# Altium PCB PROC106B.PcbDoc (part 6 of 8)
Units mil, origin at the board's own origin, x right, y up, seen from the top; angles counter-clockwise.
Board outline 4498.18 x 1060.53 mil, 8 copper layers (Top Layer, GND1, Sig1, PWR1, PWR2, Sig2, GND2, Bottom Layer), stack 69.602 mil thick; 439 components, 327 nets, 1548 pads, 843 vias.
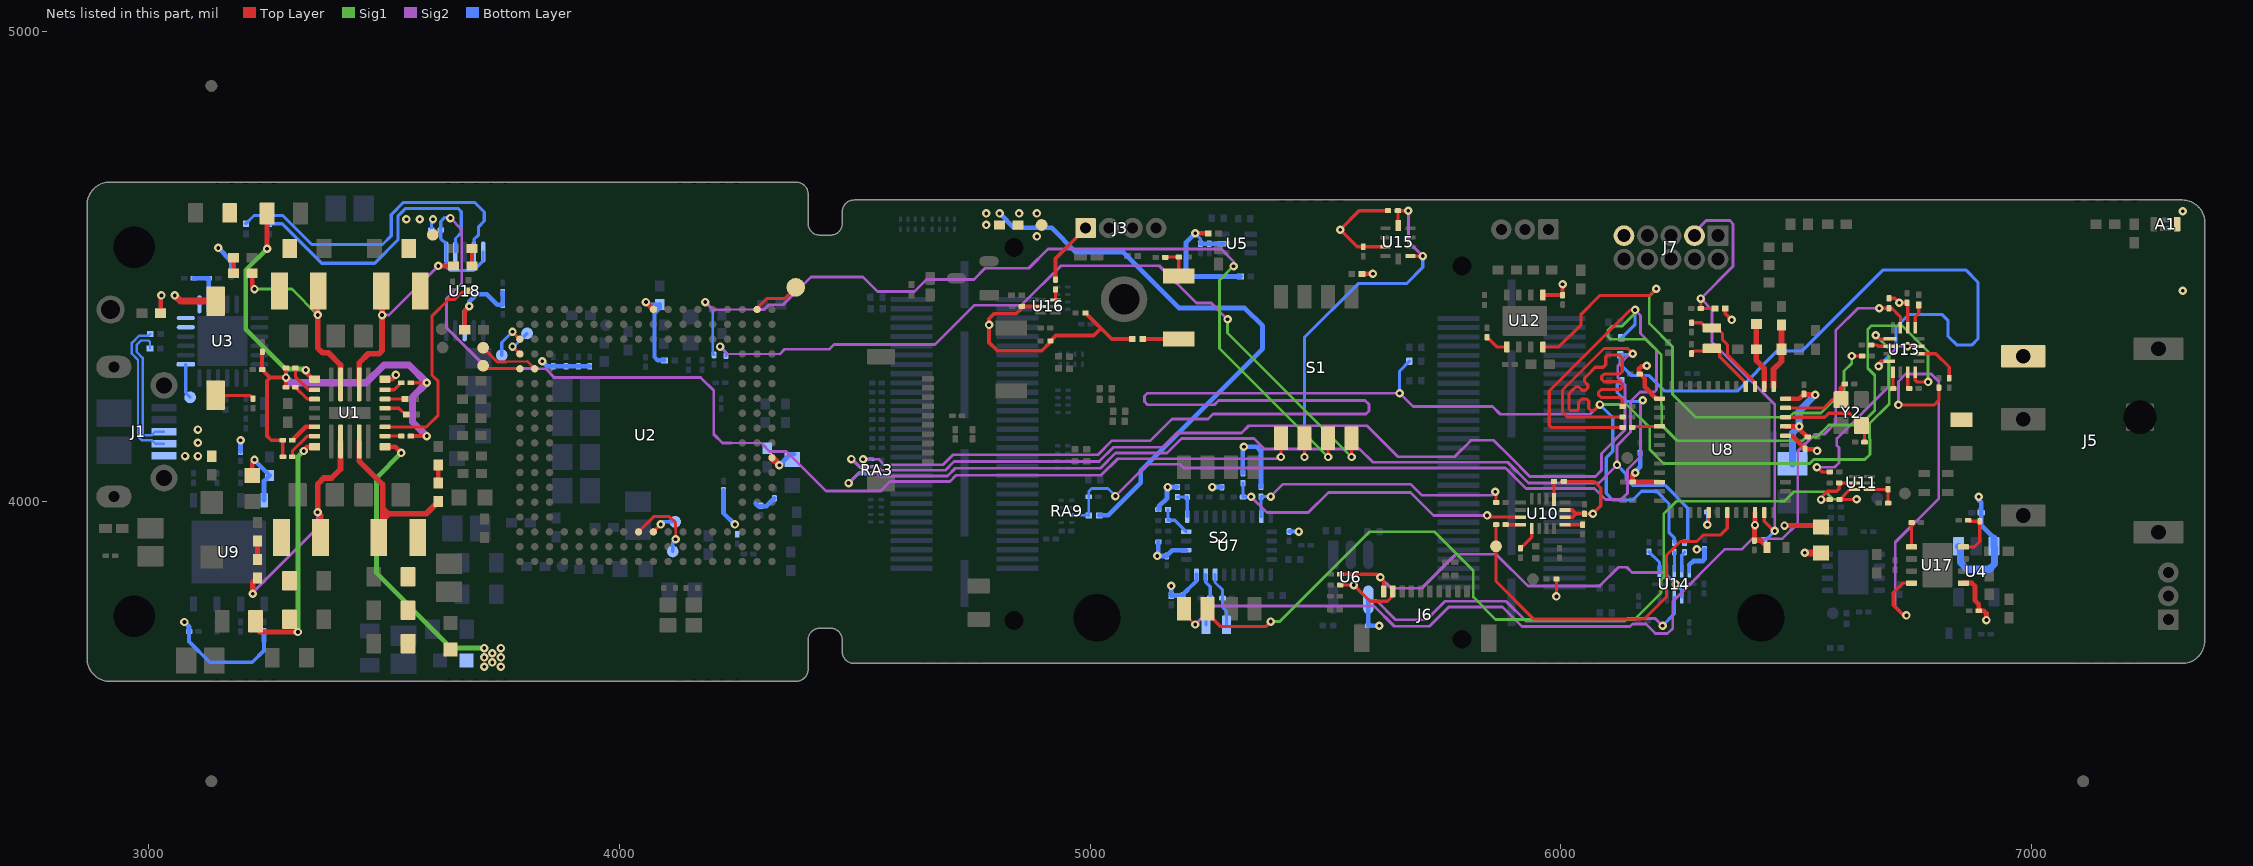
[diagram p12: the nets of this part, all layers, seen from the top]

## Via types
v1: diameter 18, hole 8, Top Layer to Bottom Layer, tented both sides, 804 vias
v2: diameter 19.68, hole 7.87, Top Layer to Bottom Layer, tented both sides, 34 vias
v3: diameter 20, hole 10, Top Layer to Bottom Layer, tented both sides, 3 vias
v4: diameter 18, hole 8, Top Layer to Bottom Layer, 1 vias
v5: diameter 17, hole 7.87, Top Layer to Bottom Layer, 1 vias

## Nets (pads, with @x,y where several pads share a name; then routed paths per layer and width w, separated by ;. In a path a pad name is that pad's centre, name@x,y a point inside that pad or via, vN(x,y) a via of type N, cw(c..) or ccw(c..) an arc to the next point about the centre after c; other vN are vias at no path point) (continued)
NetR101_1: R101.1 U10.13 | length 37.4
  Top Layer w8: U10.13@6008.8,3951.58 R101.1@6046.19,3951.58
NetR105_1: R105.1 R106.1 U11.1 | length 69.1
  Top Layer w6.7: U11.1@6655.07,4026.51 R106.1@6695.04,4026.51 R105.1@6695.04,3997.34
NetR111_1: R111.1 SW3.2 | length 77.2
  Top Layer w8: R111.1@5111.53,4345.88 SW3.2@5188.73,4345.88
NetR112_2: R112.2 U10.8 | length 31.9
  Top Layer w8: R112.2@5882.43,3951.7 5882.56,3951.58 U10.8@5914.31,3951.58
NetR113_2: R113.2 U10.9 | length 51.8
  Top Layer w6.7: R113.2@5914.31,3901.71 5937.93,3925.33 U10.9@5937.93,3943.7
NetR115_2: R115.2 R134.1 U17.8 | length 110.4
  Top Layer w6.7: U17.8@6854.9,3904.39 6878.17,3904.39 6889.78,3916 R134.1@6889.78,3961 ; R115.2@6864.81,3961 6866.81,3959 R134.1@6889.73,3959
NetR116_1: R116.1 U17.1 | length 51.7
  Top Layer w6.7: U17.1@6744.66,3904.39 6744.66,3955.88 R116.1@6744.78,3956
NetR120_1: R120.1 U17.4 | length 925.6
  Top Layer w6.7: v1(6716.81,4206) 6792.81,4206 6802.81,4216 R120.1@6802.81,4242.98 ; v1@6734.81,3758 v1(6733.81,3759) 6727.34,3759 6705.81,3780.52 6705.81,3807.03 6726.4,3827.61 U17.4@6744.66,3827.61
  Sig2 w5.95: v1(6716.81,4206) 6716.81,4256 6732.28,4271.47 6786.63,4271.47 6802.79,4255.32 6802.79,4006.91 6710.22,3914.35 6710.22,3777.92 6729.14,3759 v1(6733.81,3759)
NetR121_1: R121.1 U13.2 | length 39.5
  Top Layer w6.7: R121.1@6659.06,4333.23 6671.58,4333.23 6674.18,4330.63 U13.2@6697.44,4330.63
NetR123_1: R123.1 U12.1 | length 50.3
  Top Layer w6.7: R123.1@5843.14,4349.69 5863.49,4329.34 U12.1@5885.05,4329.34
NetR125_2: R125.2 R129.1 SW3.1 | length 69.8
  Top Layer w5.5: R129.1@5159.27,4519.45 R129.1@5159.85,4520.03 ; SW3.1@5188.33,4480.14 SW3.1@5188.73,4479.74
  Top Layer w6.7: R129.1@5159.85,4520.03 R125.2@5188.33,4520.03 SW3.1@5188.33,4480.14
NetR127_1: R127.1 U12.4 | length 1065
  Top Layer w6.7: U12.4@5961.82,4329.34 5995.51,4329.34 6042.85,4376.69 6042.85,4399.01 6082.33,4438.49 6188.48,4438.49 v1(6202.62,4452.64) ; v1(6617.81,4310) R127.1@6639.79,4310
  Sig1 w5.95: v1(6202.62,4452.64) 6187.81,4437.82 6187.81,4378.93 6237.06,4329.68 6237.06,4228.74 6285.98,4179.83 6485.43,4179.83 6494.43,4188.83 6552.42,4188.83 6601.34,4237.75 6601.34,4277.82 6617.81,4294.3 v1(6617.81,4310)
NetR128_1: R128.1 U13.5 | length 35
  Top Layer w5.5: U13.5@6705.32,4275.51 6705.32,4241.13 R128.1@6705.74,4240.71
NetR131_2: R131.2 U8.29 | length 53.8
  Top Layer w6.7: v1(6311.16,3951.46) 6313.85,3954.16 U8.29@6313.85,3977.25
  Bottom Layer w6.7: v1(6311.16,3951.46) R131.2@6311.16,3978.41
NetR136_1: R136.1 U13.7 | length 35.8
  Top Layer w6.7: U13.7@6736.81,4275.51 6736.81,4244 R136.1@6739.81,4241
NetR139_1: R139.1 U13.10 | length 102.2
  Top Layer w6.7: U13.10@6760.43,4314.88 6796.57,4314.88 6824.81,4286.64 R139.1@6824.81,4263 R139.1@6823.09,4264.72
NetR141_1: R141.1 U13.13 | length 51.3
  Top Layer w6.7: U13.13@6752.56,4370 6752.56,4392.75 6760.03,4400.22 R141.1@6760.03,4418.23
NetR160_1: R160.1 U14.10 | length 42.6
  Bottom Layer w6.7: U14.10@6256.79,3852.92 6256.79,3887.29 R160.1@6262.64,3893.14
NetR161_2: R161.2 U8.16 | length 59.1
  Top Layer w6.7: R161.2@6151.19,4158.46 6153.05,4160.32 U8.16@6209.52,4160.32
NetR166_1: R166.1 U14.9 | length 40.8
  Bottom Layer w6.7: R166.1@6240.62,3893.58 6241.04,3893.15 U14.9@6241.04,3852.92
NetR168_1: R168.1 U14.7 | length 50.9
  Bottom Layer w6.7: R168.1@6186.75,3894.37 6209.55,3871.58 U14.7@6209.55,3852.92
NetR176_1: R176.1 S3.1 | length 82.3
  Top Layer w6.7: S3.1@3142.31,4226.42 3214.75,4226.42 R176.1@3221.71,4219.46
NetR178_2: R178.2 U16.3 | length 22.1
  Top Layer w6.7: U16.3@4926.29,4429.06 R178.2@4926.29,4451.18
NetTP2_1: TP2.1 U2.C10 | length 160.9
  Top Layer w5: v1(4119.47,3920.65) 4119.47,3943.6
  Top Layer w6.7: U2.C10@4040.73,3936.4 4073.08,3968.75 4106.27,3968.75 4119.47,3955.55 4119.47,3943.6
  Bottom Layer w6.7: TP2.1@4113.44,3894.78 4113.44,3914.63 v1(4119.47,3920.65)
NetTP3_1: TP3.1 U2.C9 | length 55
  Top Layer w6.7: U2.C9@4072.23,3936.4 v1(4087.98,3952.15)
  Bottom Layer w6.7: v1(4087.98,3952.15) 4093.63,3957.8 TP3.1@4118.39,3957.8
NetTP6_1: TP6.1 U2.T18 | length 81.8
  Top Layer w6.7: v1(3773.02,4361.6) U2.T18@3788.76,4345.85
  Bottom Layer w6.7: TP6.1@3750.12,4311.58 3750.12,4338.7 v1(3773.02,4361.6)
NetTP7_1: TP7.1 U2.R18 | length 64.8
  Top Layer w6.7: v1(3773.02,4330.1) U2.R18@3788.76,4314.36
  Bottom Layer w6.7: v1(3773.02,4330.1) 3776.1,4330.1 TP7.1@3804,4358
NetTP8_1: TP8.1 U2.P17 | length 129.1
  Top Layer w5: 3759.24,4297.12 3760.35,4298.23 3804.89,4298.23
  Top Layer w6.7: TP8.1@3710.6,4327.53 3741.01,4297.12 3759.24,4297.12 ; 3804.89,4298.23 U2.P17@3820.26,4282.86
NetTP9_1: TP9.1 U2.P18 | length 81.4
  Top Layer w6.7: TP9.1@3710.6,4289.4 3716.29,4283.71 3788.76,4283.71 U2.P18@3788.76,4282.86
NetTP11_1: TP11.1 U2.V2 | length 102.4
  Top Layer w6.7: U2.V2@4291.28,4410.27 4313.18,4432.17 4351.05,4432.17 TP11.1@4374.76,4455.87
NetTP26_1: TP26.1 U3.1 | length 74
  Bottom Layer w6.7: U3.1@3078.98,4292.21 3078.98,4231.25 TP26.1@3088.22,4222.02
nRESET: C37.1 J7.3 R89.1 R91.1 U8.35 | length 976.9
  Top Layer w6.7: v1(6297.21,4431.94) C37.1@6297.21,4411.08 R89.1@6327.17,4411.08 ; U8.35@6431.96,3977.25 6431.96,3958.78 6452.3,3938.44 v1(6454.22,3938.44)
  Sig2 w5.95: J7.3@6283.84,4565.56 6283.84,4572.59 6308.82,4597.58 6358.86,4597.58 6365.86,4590.57 6365.86,4500.59 v1(6297.21,4431.94) 6321.18,4407.97 6321.18,4339.63 6454.22,4206.59 v1(6454.22,3938.44)
  Bottom Layer w6.7: R91.1@6432.17,3920.53 ccw(c6432.17,3930.54) 6439.24,3923.46 v1(6454.22,3938.44)
PGOOD: R31.2 R37.2 R155.2 RA9.7 | length 1608.1
  Sig2 w5.95: v1(5053.68,4012.45) 5121.06,4079.83 5191.42,4079.83 5198.95,4072.3 5882.26,4072.3 5926.17,4028.39 6071.12,4028.39 6094.51,4005.01 6128.26,4005.01 6141.61,4018.37 6141.61,4069.02 6169,4096.41 6169,4210.88 v1(6173.93,4215.81)
  Bottom Layer w5.95: RA9.7@4960.68,3971.89 4996.54,3971.89 R31.2@4997.02,3971.4 R37.2@4997.02,4011.07 4997.02,4022.43 5003.06,4028.46 5037.66,4028.46 v1(5053.68,4012.45)
  Bottom Layer w6.7: R155.2@6128.35,4257.57 6119.84,4249.06 6119.84,4232.32 6138.6,4213.55 6171.67,4213.55 v1(6173.93,4215.81)
PMIC_1V0: C46.2 C49.2 C54.2 L4.1 L12.1 L14.1 U1.1 | length 615.9
  Top Layer w10: U1.1@3502.28,4117.15 3523.82,4117.15 v1(3536.85,4104.13)
  Sig1 w10: v1(3536.85,4104.13) 3484.27,4051.55 3484.27,3848.75 3643.34,3689.68 v1@3717.17,3689.68
  other v1: 3712.91,3649.87 3748.46,3649.87 3730.24,3659.02 3712.91,3669.78 3748.46,3669.78 3730.24,3678.68 3712.91,3689.68 3748.46,3689.68
PMIC_1V2: C45.2 C77.2 L3.1 L13.1 U1.14 | length 457.1
  Top Layer w10: v1(3251.69,4537.83) L13.1@3251.69,4612.77 ; v1(3333.63,4280.07) 3335.17,4278.54 3335.17,4274.43 3345.86,4263.73 3349.8,4263.73 U1.14@3352.68,4260.85
  Sig1 w10: v1(3251.69,4537.83) 3206.5,4492.63 3206.5,4366.82 3290.78,4282.54 3331.16,4282.54 v1(3333.63,4280.07)
PMIC_1V8: C47.2 C48.2 L5.1 L11.1 U1.21 | length 522.1
  Top Layer w10: L11.1@3235.24,3746.61 3235.24,3723.69 v1(3317.18,3723.69) ; v1(3329.65,4108.18) 3329.65,4109.63 3337.17,4117.15 U1.21@3352.68,4117.15
  Sig1 w10: v1(3317.18,3723.69) 3317.18,4095.71 v1(3329.65,4108.18)
PMIC_3V3: C2.1 C3.1 C44.2 C87.1 C88.1 C100.2 C101.2 C102.1 C126.2 FL22.1 L2.1 R2.2 R4.1 R5.1 R7.2 R8.2 R9.1 R19.2 R21.2 R22.2 R23.2 R31.1 R40.1 R43.2 R44.2 R45.2 R59.2 R75.1 S3.2 TP5.1 U1.8 U2.H1 U2.V9 U3.5 U3.6 U3.7 U9.8 U18.8 | length 2613
  Top Layer w10: C3.1@3025.57,4400.66 3025.57,4436.95 v1(3027.25,4438.63) ; C100.2@3220.18,4055.96 3220.18,4084.7 v1(3225,4089.52) ; U1.8@3502.28,4260.85 3517.78,4260.85 3525.31,4268.38 v1(3525.31,4269.83) ; C126.2@3671.69,4365.53 3671.69,4406.19 v1(3681.35,4415.85)
  Top Layer w12: v1(4056.48,4424.59) U2.V9@4072.23,4408.84
  Top Layer w15: v1(3055.45,4438.63) 3067.65,4426.42 S3.2@3142.31,4426.42 ; U2.H1@4324.2,4093.88 v1(4339.94,4078.14)
  Bottom Layer w6.7: R19.2@3600.71,4577.6 3600.71,4597.2 v1(3604.12,4600.61)
  Bottom Layer w8: R44.2@3085.96,3724.94 3085.96,3703.29 3129.87,3659.38 3220.09,3659.38 3245.35,3684.64 3245.35,3704.34
  Bottom Layer w9: C88.1@4085.98,4412.26 4074.41,4400.69 4074.41,4307.92 4081.57,4300.76 R2.2@4095.9,4300.76
  Bottom Layer w10: v1(3076.13,3744.96) 3085.96,3735.12 R44.2@3085.96,3724.94 ; v1(3147.81,4539.54) 3175.78,4511.57 R40.1@3175.78,4498.14 ; R45.2@3195.34,4107.12 v1@3195.34,4127.87 ; v1(3225,4089.52) 3225,4088.24 C101.2@3257.08,4056.16 3245.35,4044.42 U9.8@3245.35,4003.53 ; 3245.35,3704.34 R43.2@3245.35,3724.94 ; U18.8@3671.35,4363.67 3671.35,4405.85 v1(3681.35,4415.85) 3681.35,4425.6 3696.63,4440.88 3718.65,4440.88 3740.67,4418.85 R4.1@3752.34,4418.85 ; R4.1@3752.34,4418.85 R5.1@3752.34,4445.45 ; v1(3836.01,4298.61) 3846.58,4288.04 R21.2@3859.46,4288.04 R22.2@3886.73,4288.04 R23.2@3913.05,4288.04 R59.2@3936.98,4288.04 ; v1(4056.48,4424.59) 4062.15,4418.92 C88.1@4085.98,4418.92 ; C88.1@4085.98,4412.26 C88.1@4085.98,4418.92 ; C88.1@4085.98,4419.22 C88.1@4085.98,4418.92 ; R8.2@4221.23,4024.4 4221.23,3976.38 v1(4245.46,3952.15) ; 4289.86,3996.55 4295.2,3991.21 4295.2,3990.68 4312.51,3990.68 R7.2@4329.25,4007.42 ; v1(4339.94,4078.14) 4359.11,4097.3 4362.93,4101.12 C102.1@4371,4101.12 ; v1(4807.67,4612.77) 4838.24,4582.2 4918.25,4582.2 4969.72,4530.73 5070.03,4530.73 5188.98,4411.77 5328.57,4411.77 5366.24,4374.1 5366.24,4325.35 5107.47,4066.58 5107.47,4040.46 5038.41,3971.4 R31.1@5019.07,3971.4
  other v1: 3195.34,4131.09 4779.42,4588.36 3547.73,4600.61 3575.93,4600.61 4779.42,4612.77
PMIC_CLK: R103.2 U1.3 | length 438.9
  Top Layer w6.7: U1.3@3502.28,4159.48 3590.4,4159.48 3615,4184.08 3615,4256.43 3601.71,4269.72 3601.71,4394.6 3637.2,4430.1 3650.77,4430.1 3666.52,4445.85 3676.68,4445.85 R103.2@3679.35,4448.51
PMIC_EN1: R34.1 U1.7 | length 40.7
  Top Layer w6.7: U1.7@3502.28,4238.22 3521.94,4238.22 R34.1@3536.85,4253.13
PMIC_EN2: R35.1 U1.15 | length 70.7
  Top Layer w6.7: R35.1@3311.94,4284.61 3311.94,4266.28 3340.01,4238.22 U1.15@3352.68,4238.22
PMIC_EN3: R36.1 U1.2 | length 34.6
  Top Layer w6.7: U1.2@3502.28,4139.79 R36.1@3536.85,4139.79
PMIC_NINT: R26.1 U1.19 | length 59.2
  Top Layer w10: R26.1@3305.25,4131.09 3333.63,4159.48 U1.19@3352.68,4159.48
PMIC_NRST: R33.1 U1.20 | length 72.5
  Top Layer w6.7: R33.1@3305.52,4095.96 3305.52,4108.18 3337.13,4139.79 U1.20@3352.68,4139.79
PMIC_PGOOD: R25.1 U1.16 | length 51.1
  Top Layer w6.7: R25.1@3311.94,4243.48 3336.89,4218.53 U1.16@3352.68,4218.53
PMIC_SCL: R32.2 U1.5 | length 48
  Top Layer w6.7: U1.5@3502.28,4198.85 3531.78,4198.85 R32.2@3544.85,4185.79
PMIC_SDA: R28.2 U1.6 | length 42.6
  Top Layer w5.5: R28.2@3544.85,4218.48 R28.2@3544.85,4218.48
  Top Layer w6.7: U1.6@3502.28,4218.53 R28.2@3544.85,4218.48
PMICVIO_3V3: R25.2 R26.2 R33.2 R34.2 R35.2 R36.2 R50.1 R52.2 | length 878.4
  Top Layer w8: R50.1@3241.63,4319.41 3241.09,4318.88 R52.2@3241.09,4281.06 3258.11,4264.05 ; R33.2@3285.49,4095.96 3285.23,4096.22 R26.2@3285.23,4131.09 3260.47,4131.09 3251.36,4140.2 3251.36,4257.3 3258.11,4264.05 ; R25.2@3291.92,4243.48 v1(3291.92,4264.05) ; R35.2@3291.92,4284.61 v1(3291.92,4264.05) ; R36.2@3556.87,4139.79 v1(3590.95,4139.79) ; R34.2@3556.87,4253.13 v1(3590.95,4253.13) ; 3258.11,4264.05 v1(3291.92,4264.05)
  Sig2 w15: v1(3291.92,4264.05) 3302.83,4253.13 3462.07,4253.13 3499.77,4290.83 3553.26,4290.83 v1(3590.95,4253.13) 3560.74,4222.92 3560.74,4170 v1(3590.95,4139.79)
PS0: R77.2 R93.1 U7.6 | length 62.7
  Bottom Layer w6.7: R77.2@5185.3,4010.48 R93.1@5206.3,4010.48 U7.6@5206.3,3968.74
PS1: R78.2 R98.1 U7.5 | length 71.4
  Bottom Layer w6.7: R78.2@5165.52,3984 R98.1@5165.52,3961 5179.58,3961 U7.5@5203.84,3936.75
RE: A1.1
  other v1: 7320.92,4448.37 7320.92,4617.37
RESETN: R94.1 U10.1 | length 39
  Top Layer w6.7: U10.1@5985.18,4004.73 R94.1@5985.18,4043.69
RF_N: C23.1 L6.1 U8.2 | length 139.8
  Top Layer w12: L6.1@6415.18,4377.75 6415.09,4377.66 C23.1@6415.09,4324.42 6415.09,4300.45 6431.96,4283.58 U8.2@6431.96,4244.97
RF_P: C22.2 L1.1 U8.1 | length 137.8
  Top Layer w12: U8.1@6451.65,4244.97 6451.65,4281.73 6468.52,4298.6 L1.1@6468.52,4324.41 C22.2@6468.51,4375.79
SENS_INT: R18.2 R100.1 U7.14 | length 589
  Top Layer w6.7: v1(5860.53,4021.62) 5862.41,4019.74 R100.1@5862.41,3998.82
  Sig2 w5.95: v1(5383.46,4011.31) 5409.9,4037.75 5680.81,4037.75 5704.56,4014 5852.9,4014 v1(5860.53,4021.62)
  Bottom Layer w5.5: R18.2@5362.78,4011.28 R18.2@5363.28,4010.78
  Bottom Layer w6.7: U7.14@5363.78,3968.74 5362.78,3969.74 R18.2@5362.78,4011.28 v1@5383.43,4011.28
SENS_NRST: R81.2 R97.2 U10.7 | length 677
  Top Layer w6.7: v1(5843.14,3971.4) 5846.67,3967.88 5913.76,3967.88 U10.7@5914.31,3967.32
  Sig2 w5.95: v1(5341.84,4011.07) 5375.53,3977.37 5463.23,3977.37 5506.2,4020.34 5680.27,4020.34 5729.21,3971.4 v1(5843.14,3971.4)
  Bottom Layer w5.5: v1(5341.84,4011.07) 5342.12,4010.78 5345.19,4010.78 v1@5344.89,4010.48
  Bottom Layer w6.7: R81.2@5324.41,4039.9 5324.41,4010.82 R97.2@5324.75,4010.48 5341.25,4010.48 v1(5341.84,4011.07)
SOP0: R159.2 S1.3 | length 1902
  Top Layer w6.7: v1(5505.37,4095.46) S1.3@5505.37,4135.46
  Sig1 w5.95: v1(5304.72,4500.76) 5274.9,4470.94 5274.9,4325.94 v1(5505.37,4095.46)
  Sig2 w4.5: 4223.14,4408.84 4293.24,4408.84
  Sig2 w5.95: v1(4182.46,4424.59) 4198.79,4408.27 4222.56,4408.27 ; 4293.24,4408.84 4307.81,4408.84 4317.84,4418.87 4347.94,4418.87 4406.85,4477.78 4517.43,4477.78 4548.43,4446.78 4626.58,4446.78 4652.24,4472.44 4753.09,4472.44 4776.93,4496.28 4869.62,4496.28 4910.57,4537.24 5278.49,4537.24 5304.72,4511 v1(5304.72,4500.76)
  Bottom Layer w5: v1(4182.46,4424.59) 4198.53,4408.53 4198.26,4408.26 4198.26,4315.13 R159.2@4201.23,4312.16
SOP1: R171.2 S1.4 | length 1675.6
  Top Layer w6.7: v1(5555.37,4095.46) S1.4@5555.37,4135.46
  Sig1 w5.95: v1(5292.01,4387.88) 5292.01,4358.83 v1(5555.37,4095.46)
  Sig2 w4.5: v1(4213.96,4330.1) 4229.71,4314.36 4341.35,4314.36
  Sig2 w5.95: 4341.35,4314.36 4351.45,4324.45 4446.13,4324.45 4456.22,4334.55 4670.75,4334.55 4754.18,4417.98 4854.38,4417.98 4937.96,4501.55 5146.92,4501.55 5225.73,4422.74 5257.14,4422.74 v1(5292.01,4387.88)
  Bottom Layer w6.7: v1(4213.96,4330.1) 4226.45,4317.61 R171.2@4226.45,4310.42
SPI/CAN_MUX_CTRL: R118.1 S2.1 U13.15 | length 2179.9
  Top Layer w5.5: S2.1@5199.37,3773.46 5194.37,3768.46 v1(5223.17,3739.66)
  Top Layer w6.7: v1(6676.29,4411.48) R118.1@6696.81,4411.48 6703.33,4411.48 6721.06,4393.75 U13.15@6721.06,4370
  Sig2 w5.95: v1(5223.17,3739.66) 5262.38,3778.87 5602.98,3778.87 5646.06,3735.8 5720.58,3735.8 5761.88,3777.1 5875.72,3777.1 5917.56,3735.26 6146.44,3735.26 6151.79,3740.61 6180.59,3740.61 6200.56,3720.65 6226.68,3720.65 6237.45,3731.42 6237.45,3788.77 6348.32,3899.63 6384.69,3899.63 6407.03,3921.97 6470.34,3921.97 6503.17,3954.8 6503.17,4107.57 6539.43,4143.83 6559.48,4143.83 6583.65,4168 6583.65,4364.13 6631.01,4411.48 v1(6676.29,4411.48)
SPI_CLK1: R151.2 R160.2 R161.1 RA3.2 U13.8 | length 4325
  Top Layer w6.7: R161.1@6131.17,4158.46 5979.38,4158.46 5975.27,4162.58 5975.27,4235.61 6147.42,4407.76 v1(6157.61,4407.76) ; U13.8@6752.56,4275.51 6752.56,4258.25 6755.81,4255 v1(6779.81,4255)
  Sig1 w5.95: v1(6157.61,4407.76) 6157.61,4400.83 6130.04,4373.26 6108.23,4373.26 6099.8,4364.84 6099.8,4351.52 6105.77,4345.55 6179.95,4345.55 6213.27,4312.23 6213.27,4206.95 6214.25,4205.98 6214.25,4162.84 6247.09,4130 6513.57,4130 6520.9,4137.33 6543.07,4137.33 6569.11,4163.38 6635.6,4163.38 6666.75,4194.52 6666.75,4269.04 6651.85,4283.94 6651.85,4366.63 6659.6,4374.38 6724.74,4374.38 6779.81,4319.31 v1(6779.81,4255)
  Sig2 w5.95: v1(4486.92,4040) 4509.41,4062.49 4544.84,4062.49 4552.13,4055.2 4697.06,4055.2 4713.43,4071.58 5021.63,4071.58 5053.67,4103.62 5163.24,4103.62 5194.28,4134.66 5347.84,4134.66 5369.78,4112.71 5572.06,4112.71 5600.59,4084.19 5887.19,4084.19 5931.09,4040.29 6080.55,4040.29 6118.88,4078.61 v1(6119.14,4078.61) 6119.14,4119.33 6148.08,4148.27 6148.08,4213.05 6168.31,4233.27 6198.76,4233.27 6203.07,4237.58 6203.07,4323.68 6169.29,4357.46 6169.29,4396.08 v1(6157.61,4407.76)
  Bottom Layer w6.7: v1(4486.92,4040) 4506.08,4059.16 4531.17,4059.16 4531.36,4059.36 RA3.2@4535.95,4059.36 ; v1(6119.14,4078.61) 6138,4059.75 6138,4049.46 6152.39,4035.07 6221.28,4035.07 6269.58,3986.76 6269.58,3920.11 R160.2@6262.64,3913.17 ; R151.2@6128.21,4348.48 6129,4348.48 6157.61,4377.09 v1(6157.61,4407.76)
SPI_CLK1_T: J6.1 R185.1 U14.2 | length 879.9
  Top Layer w6.7: R185.1@5531.01,3846.49 5609.9,3846.49 v1(5616.61,3839.78) 5623.32,3833.07 J6.1@5623.32,3810.06
  Sig2 w5.95: v1(5616.61,3839.78) 5639.62,3816.77 5704.53,3816.77 5776.5,3888.73 5862.44,3888.73 5929.9,3821.27 6082.33,3821.27 6122.39,3861.33 6139.78,3861.33 6151.11,3850 6219.39,3850 v1(6244.03,3825.36)
  Bottom Layer w6.7: v1(6244.03,3825.36) 6256.79,3812.6 U14.2@6256.79,3797.8
SPI_CS1: R74.1 U13.11 | length 429.1
  Top Layer w5.5: v1(6736.18,4330.63) U13.11@6760.43,4330.63
  Top Layer w6.7: v1(6543.91,4073.7) 6544.18,4073.7 6553.96,4063.92 R74.1@6571.09,4063.92
  Sig2 w5.95: v1(6543.91,4073.7) 6581.52,4073.7 6590.67,4082.85 6590.67,4115.3 6586.1,4119.86 6586.1,4135.05 6695.76,4244.71 6695.76,4309.35 6717.05,4330.63 v1(6736.18,4330.63)
SPI_CS_MUX_CTRL: R104.1 S2.2 U11.6 | length 1884.9
  Top Layer w6.7: S2.2@5249.37,3773.46 5249.37,3763.6 5277.84,3735.13 5372.76,3735.13 v1(5383.46,3745.84) ; U11.6@6623.57,4026.51 6613.5,4026.51 R104.1@6591.99,4005 6622.99,4005 6623.57,4005.59 v1(6628.05,4005.59)
  Sig1 w5.95: v1(5383.46,3745.84) 5402.84,3745.84 5593.62,3936.62 5731.27,3936.62 5813.97,3853.92 5813.97,3797.67 5861.45,3750.19 6156.27,3750.19 6212.51,3806.42 6212.51,3833.75 6218.27,3839.5 6218.27,3974.42 6245.38,4001.54 6474.92,4001.54 6495.07,4021.7 6561.94,4021.7 6578.05,4005.59 v1(6628.05,4005.59)
SPI_MISO1: R87.1 R154.1 R166.2 RA3.4 U13.1 | length 4756.8
  Top Layer w6.7: 6063.42,4193.97 6069.81,4193.97 v1(6082.75,4206.91) ; 6063.42,4194.34 6059.2,4198.55 6059.2,4214.4 6055.19,4218.42 6043.75,4218.42 6037.53,4212.2 6037.53,4197.99 6033.52,4193.97 6020.58,4193.97 6017.07,4197.49 6017.07,4229.93 6022.97,4235.83 6031.24,4244.1 6038.32,4244.1 6045.16,4237.27 6052.24,4237.27 6056.97,4241.99 6056.97,4249.07 6050.13,4255.91 6050.13,4262.99 6055.47,4268.33 6073.09,4285.95 6089.86,4285.95 6095.36,4291.45 6095.36,4308.22 6099.58,4312.44 6123.13,4312.44 6130.34,4305.22 6130.34,4276.86 6125.33,4271.85 6091.87,4271.85 6086.86,4266.84 6086.86,4260.16 6091.87,4255.15 6125.33,4255.15 6130.34,4250.14 6130.34,4243.46 6125.33,4238.45 6085.16,4238.45 6080.15,4233.44 6080.15,4226.76 6085.16,4221.75 6125.33,4221.75 6130.34,4216.74 6130.34,4203.29 R87.1@6131.17,4202.46 ; v1(6668.81,4354) 6676.43,4346.38 U13.1@6699.41,4346.38
  Sig1 w5.95: v1(6082.75,4206.91) 6139.6,4206.91 6188.75,4157.76 6188.75,4110.98 6218.01,4081.72 6528.63,4081.72 6537.08,4090.17 6645.43,4090.17 6656.26,4101 6656.26,4133.46 6655.28,4134.44 6655.28,4166.24 6697.59,4208.55 6697.59,4294.1 6697.45,4294.25 6697.45,4317.75 6697.59,4317.9 6697.59,4325.22 v1(6668.81,4354)
  Sig2 w5.95: v1(4517.69,4090.85) 4550.12,4090.85 4561.98,4078.99 4687.2,4078.99 4708.33,4100.11 5016.53,4100.11 5046.57,4130.16 5127.86,4130.16 5174.04,4176.34 5250.52,4176.34 5260.82,4186.64 5585.45,4186.64 5592.29,4193.48 5592.29,4207.43 5584.11,4215.6 5272.9,4215.6 5263.66,4206.36 5122.15,4206.36 5115.56,4212.95 5115.56,4224.91 5121.64,4230.99 v1(5657.37,4230.99) 5685.71,4202.64 5854.79,4202.64 5871.27,4186.17 6062.01,4186.17 v1(6082.75,4206.91)
  Bottom Layer w6.7: v1(4517.69,4090.85) RA3.4@4535.95,4090.85 ; v1(5657.37,4230.99) 5657.37,4278.16 R154.1@5678.13,4298.93 ; v1(6082.75,4206.91) 6110.19,4179.47 6110.19,4107.35 6096.33,4093.49 6096.33,4018.14 6110.26,4004.22 6152.95,4004.22 6171.26,4022.52 6203.4,4022.52 6229.38,3996.55 6229.38,3935.32 6240.62,3924.08 R166.2@6240.62,3913.6
SPI_MISO1_T: J6.2 R184.1 U14.3 | length 939.9
  Top Layer w6.7: R184.1@5531.18,3823.28 v1(5560.18,3823.28) 5594.55,3788.91 5631.55,3788.91 5643.01,3800.37 J6.2@5643.01,3810.06
  Sig2 w5.95: v1(5560.18,3823.28) 5592.7,3790.77 5607.91,3790.77 5648.88,3749.8 5714.78,3749.8 5753.98,3789 5883.62,3789 5925.46,3747.16 6135.69,3747.16 6141.05,3752.51 6200.45,3752.51 v1(6215.84,3737.12)
  Bottom Layer w6.7: v1(6215.84,3737.12) 6241.04,3762.32 U14.3@6241.04,3797.8
SPI_MOSI1: R86.1 R153.2 RA3.3 U13.4 | length 3868.3
  Top Layer w6.7: R86.1@6131.02,4180.57 6013.04,4180.57 6003.51,4190.11 6003.51,4237.7 6091.65,4325.84 6141.89,4325.84 v1(6152.82,4314.92) ; v1(6674.81,4288) 6674.81,4294.5 6679.45,4299.13 U13.4@6697.44,4299.13
  Sig2 w5.95: v1(4493,4091) 4494.25,4091 4510.87,4074.38 4549.77,4074.38 4557.05,4067.1 4692.13,4067.1 4711.01,4085.97 5019.2,4085.97 5049.49,4116.26 5154.64,4116.26 5184.93,4146.55 5321.51,4146.55 5336.83,4161.88 5588,4161.88 5653.79,4096.09 5774.21,4096.09 5808.94,4130.81 5857.47,4130.81 5891.66,4096.63 5891.66,4096.54 5933.94,4054.26 6073.1,4054.26 6086.14,4067.3 6086.14,4103.14 6136.19,4153.2 6136.19,4248.75 6120.66,4264.28 6120.66,4289.02 6146.56,4314.92 v1(6152.82,4314.92)
  Bottom Layer w6.7: v1(4493,4091) 4493.79,4091 4512.23,4072.56 4525.61,4072.56 4528.16,4075.11 RA3.3@4535.95,4075.11 ; v1@6152.82,4312.59 R153.2@6126.12,4312.59 6126.12,4292.58 6150.28,4268.42 6187.86,4268.42 6220.8,4235.48 6374.36,4235.48 6459.75,4320.87 6512.8,4320.87 6684.75,4492.82 6859.64,4492.82 6886.05,4466.4 6886.05,4346.31 6873.37,4333.63 6840.48,4333.63 6822.6,4351.51 6822.6,4384.73 6808.88,4398.45 6739.36,4398.45 6711.55,4370.64 6711.55,4324.74 v1(6674.81,4288)
SRDY: R112.1 TP27.1 U8.31 | length 809.2
  Top Layer w6.7: R112.1@5862.41,3951.7 5862.41,3905.96 TP27.1@5862.18,3905.74 5862.18,3831.62 5942.67,3751.13 6176.53,3751.13 6224.18,3798.77 6224.18,3886.56 6253.68,3916.06 6288.86,3916.06 6302.89,3930.09 6339.36,3930.09 6353.22,3943.95 U8.31@6353.22,3977.25
SW0: L2.2 R53.2 U1.10 | length 440.3
  Top Layer w10: v1(3615.39,4501.24) R53.2@3647.82,4501.24
  Top Layer w12: U1.10@3447.16,4249.63 3447.16,4295.44 3466.54,4314.82 3489.47,4314.82 3495.89,4321.24 v1(3495.89,4396.79) 3495.89,4452.04 L2.2@3489.45,4458.48
  Sig2 w5.95: v1(3495.89,4396.79) 3510.94,4396.79 v1(3615.39,4501.24)
SW0_CAP: C31.1 R53.1 | length 37.1
  Top Layer w8: R53.1@3687.19,4501.24 C31.1@3687.19,4538.34
SW1: L3.2 R54.2 U1.12 | length 424.2
  Top Layer w10: R54.2@3220.03,4485.56 3220.03,4457.01 v1(3225,4452.04)
  Top Layer w12: v1(3359.17,4397.16) v1@3359.17,4395.95 ; L3.2@3365.61,4448.85 3357.96,4441.2 3357.96,4397.16 v1@3359.17,4395.95 ; U1.12@3407.79,4249.63 3407.79,4291.03 3382.08,4316.74 3369.33,4316.74 3359.17,4326.9 v1@3359.17,4395.95
  Sig1 w5.95: v1(3225,4452.04) 3304.28,4452.04 v1(3359.17,4397.16)
SW1_CAP: C32.1 R54.1 | length 32.9
  Top Layer w10: R54.1@3180.66,4485.56 C32.1@3180.66,4518.49
SW2: L4.2 R55.2 U1.25 | length 339.7
  Top Layer w12: U1.25@3447.16,4128.37 3447.16,4086.98 3497.1,4037.05 3497.1,3986.55 ; L4.2@3496.99,3961.52 L4.2@3497.1,3961.63 ; R55.2@3615.39,4000.53 3589.87,3975.02 3507.05,3975.02 ; L4.2@3497.1,3961.63 3507.05,3971.58 3507.05,3975.02 ; L4.2@3497.1,3961.63 3497.1,3986.55 ; 3497.1,3986.55 3507.05,3976.61 3507.05,3975.02
SW2_CAP: C33.2 R55.1 | length 38.8
  Top Layer w10: R55.1@3615.39,4039.9 C33.2@3615.39,4078.74
SW3: L5.2 R56.2 U1.23 | length 510.6
  Top Layer w12: v1(3221.07,3804.79) 3221.07,3828.39 R56.2@3231.35,3838.68 ; L5.2@3365.51,3919.52 3365.51,3971.86 v1(3359.07,3978.3) 3359.07,4038.18 3359.6,4038.18 3372.17,4050.75 3388.9,4050.75 3407.79,4069.64 U1.23@3407.79,4128.37
  Sig2 w5.95: v1(3221.07,3804.79) 3221.07,3807.15 3359.07,3945.15 v1(3359.07,3978.3)
SW3_CAP: C34.2 R56.1 | length 38.9
  Top Layer w10: R56.1@3231.35,3878.05 C34.2@3231.35,3917
UART_MUX_CTRL1: R19.1 S1.1 U18.1 U18.5 | length 2531.7
  Top Layer w6.7: v1(5405.37,4095.46) S1.1@5405.37,4135.46
  Sig2 w4.5: 3828.67,4282.86 3842.32,4282.86 3842.94,4283.48 ; 4237.91,4125.38 4300.76,4125.38 4304.53,4121.62
  Sig2 w5.95: v1(3641.13,4602.92) 3665.03,4579.02 3665.03,4464.29 3632.83,4432.1 3632.83,4370.07 3719.32,4283.58 3827.95,4283.58 3828.67,4282.86 ; 3842.94,4283.48 3861.83,4264.58 4172.68,4264.58 4200.64,4236.63 4200.64,4143.76 4219.02,4125.38 4237.91,4125.38 ; 4304.53,4121.62 4318.78,4107.36 4354.87,4107.36 4438.8,4023.43 4555.14,4023.43 4575.02,4043.31 4701.98,4043.31 4715.52,4056.84 5023.72,4056.84 5058.6,4091.73 5401.64,4091.73 v1(5405.37,4095.46)
  Bottom Layer w6.7: v1(3641.13,4602.92) 3639.63,4604.42 3629.45,4604.42 3620.74,4595.71 R19.1@3620.74,4577.6 3620.74,4559.26 3631.98,4548.02 U18.1@3631.98,4530.99 3631.98,4499.84 3640.25,4491.57 3690.32,4491.57 3710.72,4511.98 U18.5@3710.72,4530.99
UART_MUX_CTRL2: R1.1 S1.2 U15.1 U15.5 | length 819.7
  Top Layer w6.7: v1(5455.37,4095.46) S1.2@5455.37,4135.46 ; U15.5@5654.19,4587.22 5653.69,4587.73 R1.1@5653.69,4618.56 v1(5675.9,4618.59) ; U15.1@5680.77,4522.26 v1(5706.58,4522.26)
  Sig2 w6.7: v1(5675.9,4618.59) 5675.9,4552.94 v1(5706.58,4522.26)
  Bottom Layer w6.7: v1(5455.37,4095.46) 5455.37,4349.9 5569.14,4463.66 5671.93,4463.66 5706.58,4498.31 v1(5706.58,4522.26)
USB_5V: FL2.1 J1.1
  other v1: 3077.51,4097.43 3104.7,4097.43 3104.7,4125.62 3104.7,4153.82
USB_AR_RS232RX: R63.1 U18.2 | length 614.1
  Bottom Layer w6.7: R63.1@3255.87,4590.83 3283.69,4590.83 3367.49,4507.03 3480.1,4507.03 3529.51,4556.44 3529.51,4606.69 3546.31,4623.49 3657.2,4623.49 3664,4616.69 3664,4571.71 3651.86,4559.57 ; U18.2@3651.67,4530.99 3651.67,4559.57
USB_AR_RS232TX: R62.1 U18.4 | length 705.1
  Bottom Layer w6.7: R62.1@3206.51,4591.24 3223.81,4608.54 3284.94,4608.54 3346.73,4546.75 3497,4546.75 3515.39,4565.14 3515.39,4610.32 3541.11,4636.04 3692.88,4636.04 3713.04,4615.88 3713.04,4596.78 3701.04,4584.77 3701.04,4567.45 3691.04,4557.45 U18.4@3691.04,4530.99
USB_DM: J1.2 R60.2 | length 312.5
  Bottom Layer w5: R60.2@3003.52,4356.6 2999.85,4352.92 2979.71,4352.92 2964.56,4337.77 2964.56,4314.77 2977.52,4301.8 2977.52,4138.83 2985.04,4131.3 3006.86,4131.3 3014.61,4123.56 J1.2@3032.66,4123.56
USB_DP: J1.3 R41.2 | length 292.2
  Bottom Layer w5: R41.2@3002.89,4326.25 3002.89,4339.95 2999.92,4342.92 2983.85,4342.92 2974.56,4333.63 2974.56,4318.91 2987.41,4306.05 2987.52,4305.94 2987.52,4142.97 2989.19,4141.3 3006.11,4141.3 3013.95,4149.15 J1.3@3032.66,4149.15
VBUS: R64.2 R65.2 U3.8 | length 87
  Bottom Layer w10: R64.2@3096.15,4475.15 R65.2@3127.78,4475.15 U3.8@3127.78,4419.75
VCC_BA_3V3: C5.1 C6.2 C9.2 C10.2 C11.1 C12.2 C40.1 C72.2 C105.2 C107.1 C109.2 C117.1 C119.1 C123.1 C125.1 FL22.2 J3.1 J7.9 L8.1 R1.2 R13.1 R16.1 R18.1 R38.2 R72.1 R77.1 R78.1 R80.1 R81.1 R82.1 R89.2 R94.2 R95.2 R104.2 R111.2 R118.2 R124.2 R177.1 R178.1 TP13.1 U4.1 U4.3 U5.5 U6.4 U7.3 U7.28 U10.14 U10.15 U11.5 U12.5 U13.14 U14.11 U15.8 U16.5 U17.5 | length 2941.2
  Top Layer w6.7: v1(5990.47,3799.31) R95.2@5990.47,3836.09 ; R94.2@6006.21,4043.69 6070.57,4043.69 6084.6,4029.67 6084.6,3991.13 6082.93,3989.46 6082.75,3989.46 v1(6068,3974.71) C117.1@6050.15,3974.71 ; R104.2@6570.96,4005 v1(6552.57,4005) 6552.57,4009.25 6566.03,4022.71 6585.71,4022.71 6591.11,4028.11 C40.1@6591.11,4040.29 U11.5@6623.57,4040.29 ; R118.2@6696.81,4432.52 6709.29,4432.52 v1(6718.6,4423.21) C107.1@6735.03,4423.21 6736.81,4421.43 U13.14@6736.81,4370
  Top Layer w8: U16.5@4894.79,4415.28 C72.2@4855.01,4415.28 4855.01,4411.59 4843.01,4399.58 4795.92,4399.58 4785.33,4388.99 v1(4785.33,4376.1) 4785.33,4338.93 4803.26,4320.99 4897.25,4320.99 4915.83,4339.57 R124.2@4915.83,4342.12 4927.17,4353.46 5007.56,4353.46 5022.84,4368.75 5008.56,4383.04 ; R178.1@4926.29,4472.22 4926.29,4517.21 4990.56,4581.48 J3.1@4990.29,4581.75 ; R177.1@4990.14,4401.5 5045.76,4345.88 R111.2@5089.49,4345.88 ; U15.8@5627.62,4541.95 C123.1@5580.17,4541.95 5567.55,4541.95 v1(5531.18,4578.33) 5571.41,4618.56 R1.2@5632.65,4618.56 ; U12.5@5961.82,4439.58 5961.95,4439.45 C105.2@6003.52,4439.45 ; v1(6003.44,4462.27) 6003.44,4439.53 C105.2@6003.52,4439.45 ; C105.2@6003.64,4439.33 C105.2@6003.52,4439.45 ; U10.14@6008.8,3967.32 6024.78,3967.32 6032.17,3974.71 ; U10.15@6008.8,3983.07 6023.81,3983.07 6032.17,3974.71 ; C117.1@6050.15,3974.71 6032.17,3974.71 ; R89.2@6349.22,4411.08 6349.22,4400.27 v1(6362.92,4386.56)
  Top Layer w10: v1(5223.17,4570.56) 5223.25,4570.64 R13.1@5250.79,4570.64 ; R16.1@5577.42,4484.46 5600.32,4484.46 v1(5600.59,4484.74) ; U17.5@6854.9,3827.61 6873.17,3827.61 6879.78,3821 6879.78,3790.43 6887.42,3782.79 C109.2@6887.42,3768.9 6897.81,3768.9 6903.81,3762.9 v1(6903.81,3749)
  Top Layer w15: v1@6518.19,3891.83 L8.1@6552.57,3891.83
  Bottom Layer w5.5: C11.1@5172.1,3801.28 C11.1@5172.24,3801.43 ; C9.2@5196.95,3801.43 C9.2@5197.1,3801.57 C9.2@5197.1,3803.37
  Bottom Layer w6: U14.11@6272.54,3850.95 U14.11@6272.54,3866.08
  Bottom Layer w6.7: v1(5223.17,4570.56) 5234.38,4559.36 C6.2@5234.38,4548.71 ; v1(6288.47,3899.2) C119.1@6304.91,3899.2
  Bottom Layer w8: 5207.55,3813.82 5225.98,3832.25 U7.28@5225.98,3845.7 ; v1(5259.36,4031.52) v1@5260.09,4032.25 ; R72.1@5422.76,3937.25 5422.88,3937.13 5442.81,3937.13 v1(5442.93,3937)
  Bottom Layer w10: R78.1@5144.48,3984 5145.78,3984 5146.14,3984.36 5146.14,3990.56 5163.4,4007.82 5163.4,4029.99 v1(5164.93,4031.52) R77.1@5185.3,4031.52 ; R80.1@5144.96,3915 5144.96,3887.63 v1(5142.51,3885.18) C10.2@5162.69,3885.18 5174.88,3897.38 U7.3@5203.84,3897.38 ; C11.1@5172.1,3801.43 v1(5172.1,3821.6) ; C11.1@5172.24,3801.43 C9.2@5196.95,3801.43 ; C9.2@5197.1,3803.37 5207.55,3813.82 ; v1(5223.17,4570.56) 5203.84,4551.22 5203.84,4492.98 5218,4478.82 R38.2@5319.45,4478.82 ; C6.2@5234.38,4548.71 C125.1@5252.95,4548.71 U5.5@5283.23,4548.71 ; v1(5259.36,4031.52) R82.1@5279.72,4031.52 ; R81.1@5324.41,4060.94 5324.41,4114.87 v1(5326.65,4117.12) 5353.72,4117.12 5362.78,4108.06 R18.1@5362.78,4032.31 ; U6.4@5590.94,3792.16 C12.2@5590.94,3737.11 v1(5613.91,3737.11) ; U14.11@6272.54,3866.08 6280.92,3874.46 6301.2,3874.46 6304.91,3878.17 C119.1@6304.91,3899.2 ; v1(6887.74,4011.25) 6887.74,4003.81 6892.68,3998.87 C5.1@6892.68,3977 6892.68,3950.48 U4.3@6919.58,3923.58
  Bottom Layer w15: U4.1@6844.78,3905.76 6848.43,3902.11 6848.43,3871.38 6862.81,3857 6909.81,3857 6920.81,3868 6920.81,3904.53 U4.3@6919.58,3905.76 U4.3@6919.58,3923.58
  other v1: 6518.19,3892.23 4886.95,4563.95 4849.03,4612.77 4886.95,4612.77
VDDR: C29.1 C35.1 C36.1 L7.2 U8.45 U8.48 | length 294.5
  Top Layer w10: U8.45@6477.24,4160.32 6477.31,4160.39 6506.11,4160.39 v1(6506.18,4160.46) 6507.71,4158.93 6507.71,4153.36 6522.85,4138.22 C35.1@6524.64,4138.22 ; U8.48@6477.24,4219.38 6506.43,4219.38 C36.1@6516.27,4229.22 6516.27,4228.39 6516.44,4228.22 6539.09,4228.22 v1(6540.09,4227.23)
  Bottom Layer w15: L7.2@6491.96,4080.83 C29.1@6491.97,4137.37 6491.97,4146.25 v1(6506.18,4160.46) 6506.18,4193.32 v1(6540.09,4227.23)
VDDS: C25.1 C26.1 C27.1 C28.1 C86.1 L8.2 R110.2 U8.13 U8.22 U8.34 U8.44 | length 487.2
  Top Layer w10: v1@6157.19,4062.2 6152.19,4057.2 C26.1@6152.19,4042.21 U8.22@6209.52,4042.21 ; v1(6182.47,4289.2) 6180.94,4287.67 6170.56,4287.67 6165.61,4282.72 6165.61,4271.56 6165.78,4271.39 C25.1@6167.35,4271.39 6169.15,4271.39 6178.1,4262.44 6178.1,4244.27 6202.99,4219.38 U8.13@6209.52,4219.38 ; U8.34@6412.28,3977.25 v1(6412.28,3950.73) 6411.02,3949.47 6411.02,3918.09 C86.1@6410.84,3917.92 6424.27,3917.92 6438.05,3904.14 C28.1@6438.05,3903.24 ; v1(6474.93,3949.86) 6549.37,3949.86 L8.2@6552.57,3946.66 ; U8.44@6477.24,4140.64 6477.51,4140.36 6491.23,4140.36 6516.45,4115.15 6518.25,4115.15 6518.42,4114.97 C27.1@6518.42,4113.17 6518.42,4112.06 6518.59,4111.89 6538.59,4111.89 6542.02,4108.46 v1(6544.18,4108.46)
  Bottom Layer w10: v1(6158.08,4062.2) 6158.08,4064.36 6168.27,4074.55 R110.2@6168.27,4104.23
VIN_5V_B: J5.1 L15.1
X32K_Q1: C19.1 U8.3 Y3.1 | length 216.5
  Top Layer w6.7: C19.1@6277.6,4380.71 6298.4,4380.71 6309.53,4369.58 Y3.1@6320.71,4369.58 6331.42,4369.58 6343.35,4357.65 6343.35,4344.38 6353.86,4333.87 6353.86,4312.81 6412.28,4254.39 U8.3@6412.28,4244.97
X32K_Q2: C20.1 U8.4 Y3.2 | length 164.5
  Top Layer w6.7: C20.1@6277.6,4315.14 6282.8,4320.34 6291.16,4320.34 6291.2,4320.37 6304.91,4320.37 6304.94,4320.34 6314.77,4320.34 Y3.2@6320.71,4326.27 6330.35,4326.27 6337.44,4319.18 6337.44,4308.18 6392.59,4253.03 U8.4@6392.59,4244.97
X48M_N: C18.1 U8.46 Y2.3 | length 213.8
  Top Layer w6.7: U8.46@6477.24,4180.01 6560.18,4180.01 6568.53,4188.35 6613.06,4188.35 6638.36,4163.06 6644.88,4156.53 C18.1@6644.88,4127.04
X48M_P: C17.1 U8.47 Y2.1 | length 162.1
  Top Layer w6.7: U8.47@6477.24,4199.69 6559.04,4199.69 6576.76,4217.41 Y2.1@6595.05,4217.41
  Top Layer w10: Y2.1@6595.05,4217.41 6595.05,4242.62 C17.1@6603.32,4250.88
XIN32: C38.1 U7.27 Y4.1 | length 114.6
  Bottom Layer w6.7: U7.27@5245.67,3845.7 5245.67,3829.53 5255.25,3819.94 C38.1@5255.25,3795.56 5255.25,3772.96 5246.17,3763.87 Y4.1@5246.17,3738.88
XOUT32: C39.1 U7.26 Y4.2 | length 116.8
  Bottom Layer w6.7: U7.26@5265.35,3845.7 5265.35,3828.79 5281.32,3812.82 C39.1@5281.32,3795.56 5281.32,3776.47 5289.47,3768.32 Y4.2@5289.47,3738.88
pads on no net: A1.2-3 A1.5-6 Designator1. Designator1_2. Designator6. Designator7. Designator7_1. Designator8. Designator22_1. Designator23. FID1.1 FID2.1 FID3.1 FID4.1 FID5.1 FID6.1 J1.4 J2.1 J2.3 J2.4 J2.5 J2.6 J2.7 J2.9 J2.MH1 J2.MH2 J4.4 J5.MH1 J6.4 J11.1 J11.2 J11.3 J11.4 J11.5 J11.6 J11.8 J11.14 J11.20 J11.22 J11.32 J11.34 J11.35 J11.37 J11.38 J11.39 J11.40 J11.41 J11.43 J11.45 J11.47 J11.49 J11.MH1 J11.MH2 RA2.1 RA2.8 RA5.4 RA5.5 S2.4 S2.5 U1. U2.A3 U2.A4 U2.B3 U2.B4 U2.B5 U2.C3 U2.C4 U2.C5 U3.10 U3.11 U3.14 U3.15 U3.16 U3.18 U3.19 U3.21 U3.22 U3.23 U3.24 U7.1 U7.7 U7.8 U7.12 U7.13 U7.15 U7.16 U7.18 U7.21 U7.22 U7.23 U7.24 U8.5 U8.6 U8.9 U8.10 U8.12 U8.18 U8.19 U8.20 U8.28 U8.32 U8.36 U8.37 U8.38 U8.39 U8.40 U8.41 U8.42 U8.43 U9. U12.9@5898.44,4384.46 U12.9@5948.44,4384.46 U17.9@6799.78,3841 U17.9@6799.78,3891 U19.9@6621.18,3825.66 U19.9@6621.18,3875.27

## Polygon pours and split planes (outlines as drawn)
AR_1P0_RF1 on Top Layer "Top Layer-AR_1P0_RF1" (solid, remove dead copper, pour order 649): 3622.84,3727.73 3778.92,3727.73 3778.92,3831.26 3610.6,3831.26 3610.6,3739.75
GND on Top Layer "Sig1-GND 2" (solid, remove dead copper, pour order 832): 6459.32,4229.38 6459.32,3992.83 6215.85,3992.83 6215.85,4229.38 6299.65,4229.38 6299.65,4641.38 4400.86,4641.38 4400.86,3656.87 7367.76,3656.87 7367.76,4358 7219.14,4358 7219.14,4488.02 6618.99,4488.02 6618.99,4229.38
GND on Top Layer "Top Layer-GND 1" (solid, pour order 860): 3352.02,3690.19 3363.7,3701.87 3363.7,3858.21 3395,3889.52 3395,3954.52 3375,3974.52 3375,4039.52 3401.62,4039.52 3420.04,4057.94 3419.76,4163.82 3437,4163.25 3437,4055.41 3451.95,4039.52 3480,4039.52 3480,3974.52 3460,3954.52 3460,3889.52 3492.88,3856.64 3492.88,3676.94 3431.96,3676.94 3416.35,3661.33 3416.35,3618.9 3322.61,3618.9 3322.61,3690.19
PMIC_1V0 on Top Layer "Top Layer-PMIC_1V0" (solid, pour order 651): 3521.27,3650.25 3552.62,3618.9 3763,3618.9 3763,3700.57 3607.78,3700.57 3582.57,3725.77 3582.57,3878.09 3588.82,3884.34 3588.82,3962.83 3521.27,3962.83
GND on Top Layer "Top Layer-GND 5" (solid, remove dead copper, pour order 836): 3256.43,4679.43 3256.43,3618.9 2869.58,3618.9 2869.58,4679.43
AR_1P0_RF1 on Top Layer "Top Layer-AR_1P0_RF1 1" (solid, remove dead copper, pour order 180): 3693.6,4193.03 3735.64,4193.03 3777.43,4151.23 3862.16,4151.23 3862.16,4117.46 3693.6,4117.46
AR_1P0_RF2 on Top Layer "Top Layer-AR_1P0_RF2" (solid, remove dead copper, pour order 184): 3692.8,4107.78 3864.62,4107.78 3864.62,4045.8 3755.39,4045.8 3755.39,3989.76 3692.8,3989.76
VIN_5V_B on Top Layer "      " (solid, pour order 186): 6917.66,4278.57 7030.69,4278.57 7030.69,4341.43 6842.63,4341.43 6842.63,4209.57 6819.3,4186.24 6819.3,4158.51 6905.76,4158.51 6905.76,4266.67
GND on Top Layer "Top Layer-GND" (solid, pour order 862): 3454.24,4326.81 3479.96,4326.81 3479.96,4403.49 3459.96,4423.49 3459.96,4476.27 3489.96,4506.27 3489.96,4574.41 3364.49,4574.41 3364.49,4506.79 3394.96,4476.32 3394.96,4423.49 3374.96,4403.49 3374.96,4326.81 3400.35,4326.81 3410.28,4316.88 3419,4308.02 3419,4214.87 3439,4214.87 3439,4311.57
GND on Top Layer "Top Layer-GND 6" (solid, pour order 844): 3427.48,4128.37
5V_IN on Top Layer "TOP-5V_IN 1" (solid, pour order 166): 4492.93,3778 4588.97,3778 4588.97,3679.21 4492.93,3679.21
NetJ2_2 on Top Layer "Top Layer-NetJ2_2" (solid, pour order 828): 4806.74,3770.35 4806.74,3792.4 4729.81,3792.4 4729.81,3873.98 4913.31,3873.98 4913.31,3825.1 cw(c4883.91,3825.09) 4904.69,3804.3 4904.06,3803.66 ccw(c4923.41,3784.3) 4896.04,3784.3 4896.04,3770.35
5V_IN_B on Top Layer "Top Layer-5V_IN_B" (solid, remove dead copper, pour order 647): 6818.45,4144.21 6818.52,4133.31 6878.93,4133.31 6878.93,4115.45 6878.93,4045.97 6838.21,4045.97 6710.21,4045.97 6710.21,4144.21
5V_HD_IN on Top Layer "TOP-5V_IN_SW" (solid, pour order 446): 4795.77,3781.1 4629.86,3781.1 4629.86,3675.1 4795.77,3675.1
GND on Top Layer "Top Layer-GND 2" (solid, remove dead copper, pour order 798): 3604.51,3912.12 3610.61,3906.02 3610.61,3847.24 3680.34,3847.24 3680.34,3895.86 3680.34,4191.13 3624.87,4191.13 3624.87,4160.79 3636.76,4160.79 3636.76,3977 3604.51,3977
5V_IN on Top Layer "Top Layer-5V_IN 2" (solid, remove dead copper, pour order 671): 3500.98,4077.21 3500.98,4050.06 3516.26,4050.06 3516.25,3987.15 3594.49,3987.15 3594.49,4077.21
PMIC_1V8 on Top Layer "Top Layer-PMIC_1V8" (solid, pour order 816): 3207,3715.57 3329.65,3715.57 3329.65,3966.06 3255,3966.06 3255,3793.82 3246.82,3784.52 3207,3784.52
5V_IN on Top Layer "Top Layer-5V_IN" (solid, remove dead copper, pour order 814): 3508.62,4391.71 3586.15,4391.71 3586.15,4315.47 3580.69,4310.01 3514.84,4310.01 3508.62,4316.23
PMIC_1V2 on Top Layer "Top Layer-PMIC_1V2" (solid, remove dead copper, pour order 665): 3233.33,4551.48 3241.14,4543.68 3241.09,4412.42 3311.94,4412.42 3311.94,4573.58 3294.31,4573.58 3270.51,4597.88 3270.29,4661.34 3148.38,4661.34 3148.38,4551.48
AR_1P2 on Top Layer "Top Layer-AR_1P2" (solid, remove dead copper, pour order 659): 3299.36,4586.16 3287.57,4597.95 3287.23,4598.23 3287.23,4667.19 3369.41,4667.19 3369.41,4586.16
GND on Top Layer "Top Layer-GND 4" (solid, remove dead copper, pour order 810): 3631,4270 3682,4270 3682,4205 3631,4205
GND on Top Layer " " (solid, remove dead copper, pour order 752): 3883.7,3985.39 4211.48,3985.39 4211.48,4302.34 3883.7,4302.34
VCC_BA_3V3 on Top Layer "Top Layer-VCC_BA_3V3" (solid, remove dead copper, pour order 768): 4832.84,4637.18 4910.97,4637.18 4918.95,4629.19 4918.95,4544.77 4916.82,4542.64 4849.86,4542.64 4832.84,4559.66
PMIC_3V3 on Top Layer "Top Layer-PMIC_3V3 2" (solid, remove dead copper, pour order 766): 4819.62,4637.18 4819.62,4563.95 4766.02,4563.95 4766.02,4637.18
PMIC_3V3 on Top Layer "Top Layer-PMIC_3V3 1" (solid, remove dead copper, pour order 754): 3010.94,4386.79 3010.94,4443.24 3027.09,4459.4 3166.55,4459.4 3166.55,4386.79
USB_5V on Top Layer "Top Layer-USB_5V" (solid, pour order 750): 3063.11,4081.47 3153.22,4081.47 3153.22,4171.61 3063.11,4171.61
NetD1_2 on Top Layer "Top Layer-NetD1_2" (solid, pour order 736): 3089.22,4074.59 3164.79,4074.59 3164.79,3955 3089.22,3955
5V_IN on Top Layer "Top Layer-5V_IN 4" (solid, pour order 675): 2922.29,3910 3060.17,3910 3083.17,3933 3179.96,3933 3179.96,3827.52 2922.29,3827.52
5V_IN on Top Layer "Top Layer-5V_IN 3" (solid, remove dead copper, pour order 673): 3353.98,4077.21 3353.98,4050.06 3338.7,4050.06 3338.7,3978.23 3260.47,3978.23 3260.47,4077.21
AR_1V8 on Top Layer "Top Layer-AR_1V8" (solid, remove dead copper, pour order 669): 3197.24,3784.52 3197.24,3697.61 3285.71,3697.61 3285.71,3618.9 3114.34,3618.9 3114.34,3784.52
5V_IN on Top Layer "Top Layer-5V_IN 1" (solid, remove dead copper, pour order 667): 3353.98,4300.8 3353.98,4327.95 3338.7,4327.95 3338.7,4399.78 3260.47,4399.78 3260.47,4300.8
PMIC_3V3 on Top Layer "Top Layer-PMIC_3V3" (solid, remove dead copper, pour order 657): 3536.85,4651.65 3536.85,4413.49 3624.53,4413.49 3624.53,4651.65
RE on Top Layer "Bottom Layer-RE" (solid, remove dead copper, pour order 334): 7331.54,4438.37 7307.92,4438.37 7307.92,4627.35 7331.54,4627.35
GND on Top Layer " " (solid, remove dead copper, pour order 495): 7233.51,4641.4 7233.51,4515.96 6600.52,4515.97 6600.52,4242.13 6357.55,4242.12 6357.55,4641.29
no net on Top Layer " " (solid, remove dead copper, pour order 643): 6030.79,4320.34
no net on Top Layer "Top Layer-No Net" (solid, remove dead copper, pour order 645): 6335,4190
no net on Top Layer "TOP-No Net 2" (solid, pour order 489): 6159.44,4021.48
no net on Top Layer "TOP-No Net" (solid, pour order 430): 6163.15,4205.41
GND on Bottom Layer "Bottom Layer-GND" (solid, remove dead copper, pour order 878): 4154.92,3910.72 4160.18,3905.46 4197.05,3905.46 4218.8,3883.71 4223.68,3878.83 4223.68,3835.22 4223.68,3780.47 4119.65,3780.47 4119.65,3826.3 3814.73,3826.94 3814.73,3619 4400.86,3619 4400.86,3656.87 7367.76,3656.87 7367.76,4357.96 7230.16,4357.96 7230.16,4641.43 4400.86,4641.43 4400.86,4286.48 4119.65,4287.07 4119.65,4266.74 4008.5,4266.74 4008.5,4031.3 4119.65,4031.3 4119.65,3911.66 4120.78,3910.72
GND on Bottom Layer "GND" (solid, pour order 894): 4078.16,3900.61 4093.83,3900.61 4096.97,3897.47 4096.97,3885.14 4100.94,3881.17 4129.99,3881.17 4147.13,3898.31 4169.52,3898.31 4171.36,3896.47 4171.36,3866.63 4169.51,3864.78 4083.4,3864.78 4078.16,3870.03
GND on Bottom Layer "GND" (solid, pour order 892): 3899.59,3848.81 3901.99,3846.41 3931.54,3846.41 3936.73,3851.62 3936.73,3876.73 3944.38,3884.38 3970.71,3910.72 3970.67,3951.94 3962.76,3959.85 3928.09,3959.85 3922.3,3954.05 3922.3,3896.41 3899.59,3873.69
GND on Bottom Layer "GND" (solid, pour order 890): 3982.03,3900.86 4034,3901.01 4037.85,3897.16 4037.85,3839.65 4034.09,3835.9 3981.77,3835.9 3977.6,3840.07 3977.6,3896.44
GND on Bottom Layer "GND" (solid, remove dead copper, pour order 888): 3763.2,3991.74 3765.61,3994.16 3846.5,3994.16 3860.43,3980.23 3877.77,3980.23 3881.32,3976.68 3881.32,3955.21 3871.66,3945.55 3843.8,3945.55 3840.67,3942.42 3796.6,3942.42 3787.65,3951.37 3787.65,3969.29 3784.09,3972.84 3767.75,3972.84 3763.48,3977.1 3763.48,3991.6
GND on Bottom Layer "3v3" (solid, pour order 884): 3655.99,4207.12 3837.93,4207.12 3846.85,4198.19 3846.85,4167.5 3843.52,4164.17 3684.96,4164.17 3681.27,4160.48 3681.27,4134.16 3673.88,4126.78 3634.36,4126.78 3629.15,4131.99 3629.15,4180.28
AR_1P0_RF2 on Bottom Layer "Bottom Layer-AR_1P0_RF2" (solid, remove dead copper, pour order 715): 3584.17,3684.8 3575,3693.97 3447.64,3693.97 3447.64,3827.02 3463.59,3842.97 3463.59,4114.97 3850.57,4114.97 3850.57,4123.81 3901.57,4123.81 3901.57,3988.64 3857.37,3988.64 3840.08,4005.93 3615.55,4005.93 3560.24,3950.62 3560.24,3809.89 3630.87,3738.52 3630.87,3632.23 3584.17,3632.23
GND on Bottom Layer "3v3" (solid, pour order 882): 3598.93,3925.22 3603.65,3920.5 3663.91,3920.5 3669,3925.22 3669,3987.35 3665.53,3990.82 3608,3990.82 3608.2,3990.33 3598.93,3981.06
GND on Bottom Layer "Bottom Layer-GND 10" (solid, pour order 880): 3569.04,3677.61 3443.4,3677.61 3428.01,3662.22 3428.01,3626.7 3569.04,3626.7
GND on Bottom Layer "Bottom Layer-GND 1" (solid, remove dead copper, pour order 872): 4400.86,4680.01 4400.86,4459.04 3464.91,4459.04 3464.91,4681.06
GND on Bottom Layer "Bottom Layer-GND 4" (solid, remove dead copper, pour order 868): 3453.87,3851.35 3435.67,3833.16 3435.67,3689.11 3413.42,3666.86 3413.42,3618.93 3291.07,3619 2869.59,3619 2869.27,4679.44 3599.38,4679.44 3599.38,4171.06 3567.24,4138.92 3468.46,4138.92 3453.87,4124.33
GND on Bottom Layer "Bottom Layer-GND 6" (solid, remove dead copper, pour order 866): 3004.61,4191.68 3001.51,4194.78 3001.51,4270.43 3010.47,4279.38 3054.7,4279.38 3062.57,4271.51 3062.57,4193.36 3060.81,4191.61 3004.87,4191.61
GND on Bottom Layer "Bottom Layer-GND 7" (solid, pour order 858): 3915.95,4201.08 3915.95,4202.85 3996.51,4202.85 3996.51,4133.63 3915.95,4133.63
VDDR on Bottom Layer "Bottom Layer-VDDR" (solid, pour order 856): 6453.28,4049.95
GND on Bottom Layer "Bottom Layer-GND 7" (solid, pour order 826): 3915.95,4273.08 3915.95,4274.85 3996.51,4274.85 3996.51,4211.67 3915.95,4211.67
GND on Bottom Layer "Bottom Layer-GND 8" (solid, pour order 824): 4008.94,4020.83 4008.81,4023.67 4061.51,4023.67 4109.07,4023.49 4109.07,3980.27 4008.94,3980.27
GND on Bottom Layer "Bottom Layer-GND 9" (solid, pour order 822): 4008.5,4031.3
NetJ2_2 on Bottom Layer "Bottom Layer-NetJ2_2" (solid, pour order 812): 4801.23,3864.59 4947.97,3864.59 4947.97,3855.45 cw(c4942.84,3855.45) 4942.84,3850.31 4920.85,3829.22 4908.1,3808.02 4896.04,3778.48 4895.06,3771.05 4894.92,3771.19 4802.41,3771.19 4801.3,3772.3 4801.3,3864.69
no net on Bottom Layer "Bottom Layer-No Net 1" (solid, pour order 796): 3254.94,3794.88 3255,3784.52 3245.82,3784.52
USB_5V on Bottom Layer "Bottom Layer-USB_5V" (solid, remove dead copper, pour order 784): 3065.42,4075.83 3058.31,4075.83 cw(c3058.31,4081.29) 3052.85,4081.29 3001.1,4081.29 3001.1,4109.86 3066.9,4109.86 3070.95,4114.47 3070.95,4168.22 3144.18,4168.22 3144.18,4088.9 3131.11,4075.83
PMIC_3V3 on Bottom Layer "Bottom Layer-PMICOUT_3V3" (solid, remove dead copper, pour order 693): 4308.45,4059.57 4308.45,4015.14 4292.6,4015.14 4292.6,3991.49 4292.6,3925.72 4214.41,3925.72 4214.41,4078.58 4264.91,4129.09 4382.66,4129.09 4382.67,4059.57
GND on Bottom Layer "Bottom Layer-GND 3" (solid, remove dead copper, pour order 760): 3437.8,4669.84 3522.45,4669.84 3522.45,4586.72 3437.8,4586.72
GND on Bottom Layer "Bottom Layer-GND 5" (solid, remove dead copper, pour order 756): 3589.51,3885.19 3589.51,3816.34 3622.06,3783.79 3660.04,3745.8 3660.04,3708.73 3691.76,3708.73 3691.76,3893.86 3678.45,3907.17 3611.49,3907.17
GND on Bottom Layer "Bottom Layer-GND 2" (solid, remove dead copper, pour order 748): 3921.61,4124.36 3995.34,4124.36 3995.34,3981.19 3921.61,3981.19
AR_1P2 on Bottom Layer "Bottom Layer-AR_1P2" (solid, remove dead copper, pour order 742): 3283.69,4679.43 3417.05,4679.43 3417.05,4582.18 3283.69,4582.18
5V_IN on Bottom Layer "Bottom Layer-5V_IN" (solid, remove dead copper, pour order 721): 2969.58,3908.01 3085.96,3908.01 3085.96,3827.52 2969.58,3827.52
PMIC_1V0 on Bottom Layer "Bottom Layer-PMIC_1V0" (solid, remove dead copper, pour order 719): 3710.58,3701.2 3698.85,3689.47 3661.67,3689.47 3661.67,3629.17 3763.64,3629.17 3763.64,3701.2
no net on Bottom Layer "BOTTOM-No Net 1" (solid, remove dead copper, pour order 709): 3713.85,4118.01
